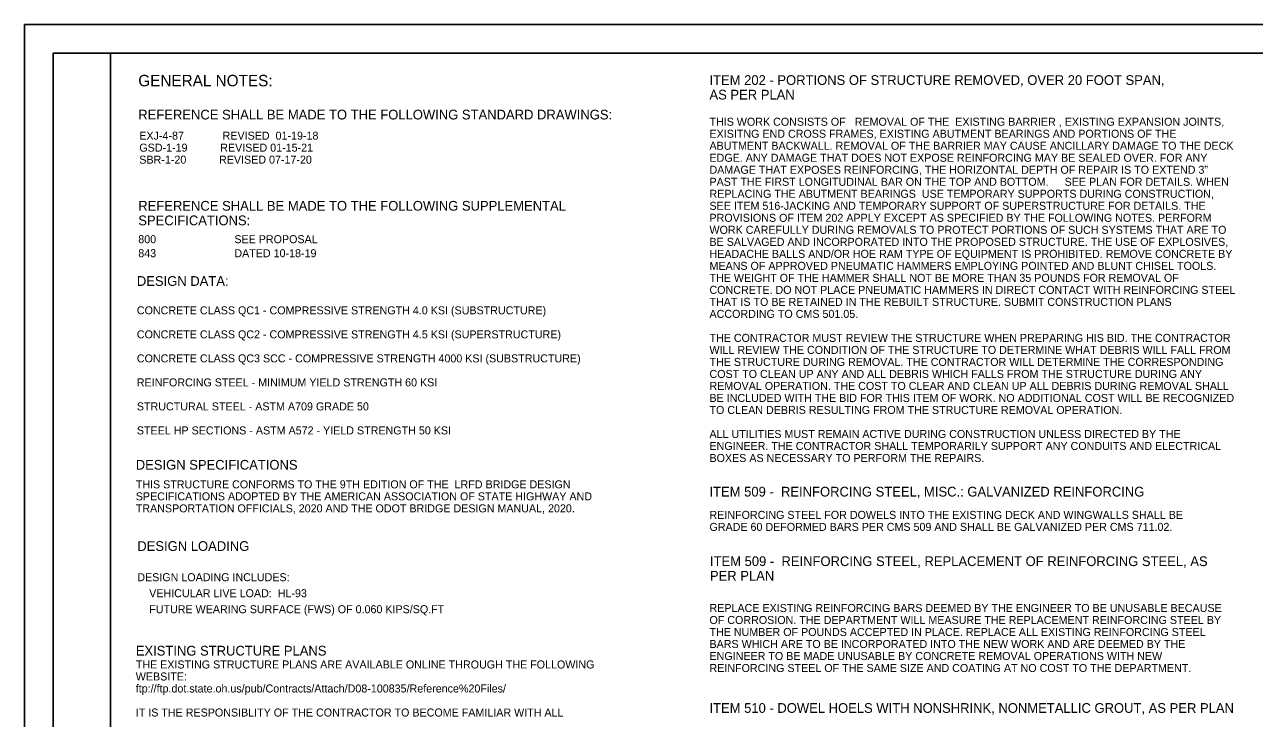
# Model space of a CAD drawing. Extents: x -17.8 to 35.4, y -13.8 to 33.2.
# Drawn here: x 0 to 21.5, y 9.87 to 22 of the extents above; entities that cross this region are included whole.
import ezdxf

# ---------------------------------------------------------------- set-up
doc = ezdxf.new("R2010")
doc.units = 0
for name, color, linetype in [('BR_P_Gen_Text', 7, 'Continuous'), ('SH_Border', 7, 'Continuous'), ('SH_Cut_Line', 7, 'Continuous'), ('SH_Text', 7, 'Continuous')]:
    doc.layers.add(name, color=color, linetype=linetype)

msp = doc.modelspace()

# ---------------------------------------------------------------- linework, layer by layer
at = {"layer": 'SH_Border'}
for points in [[(0.5, 21.5), (1.5, 21.5), (1.5, 0.5), (0.5, 0.5)], [(1.5, 21.5), (33.5, 21.5), (33.5, 0.5), (1.5, 0.5)]]:
    msp.add_lwpolyline(points, close=True, dxfattribs=at)
at = {"layer": 'SH_Cut_Line'}
msp.add_lwpolyline([(0, 0), (34, 0), (34, 22), (0, 22)], close=True, dxfattribs=at)

# ---------------------------------------------------------------- texts
at = {"layer": 'BR_P_Gen_Text'}
for s, height, p in [('GENERAL NOTES:', 0.2, (1.988, 20.921)), ('ITEM 202 - PORTIONS OF STRUCTURE REMOVED, OVER 20 FOOT SPAN, ', 0.17, (11.976, 20.945)), ('AS PER PLAN', 0.17, (11.976, 20.69)), ('REFERENCE SHALL BE MADE TO THE FOLLOWING STANDARD DRAWINGS:', 0.17, (1.988, 20.341)), ('THIS WORK CONSISTS OF ', 0.14, (11.976, 20.231)), ('REMOVAL OF THE  EXISTING BARRIER , EXISTING EXPANSION JOINTS, ', 0.14, (14.516, 20.231)), ('EXISITNG END CROSS FRAMES, EXISTING ABUTMENT BEARINGS AND PORTIONS OF THE ', 0.14, (11.976, 20.021)), ('ABUTMENT BACKWALL. REMOVAL OF THE BARRIER MAY CAUSE ANCILLARY DAMAGE TO THE DECK ', 0.14, (11.976, 19.811)), ('EDGE. ANY DAMAGE THAT DOES NOT EXPOSE REINFORCING MAY BE SEALED OVER. FOR ANY ', 0.14, (11.976, 19.601)), ('DAMAGE THAT EXPOSES REINFORCING, THE HORIZONTAL DEPTH OF REPAIR IS TO EXTEND 3” ', 0.14, (11.976, 19.391)), ('PAST THE FIRST LONGITUDINAL BAR ON THE TOP AND BOTTOM. ', 0.14, (11.976, 19.181)), ('SEE PLAN FOR DETAILS. WHEN ', 0.14, (18.186, 19.181)), ('REPLACING THE ABUTMENT BEARINGS  USE TEMPORARY SUPPORTS DURING CONSTRUCTION, ', 0.14, (11.976, 18.971)), ('REFERENCE SHALL BE MADE TO THE FOLLOWING SUPPLEMENTAL ', 0.17, (1.988, 18.746)), ('SEE ITEM 516-JACKING AND TEMPORARY SUPPORT OF SUPERSTRUCTURE FOR DETAILS. THE ', 0.14, (11.976, 18.761)), ('SPECIFICATIONS:', 0.17, (1.988, 18.491)), ('PROVISIONS OF ITEM 202 APPLY EXCEPT AS SPECIFIED BY THE FOLLOWING NOTES. PERFORM ', 0.14, (11.976, 18.551)), ('800', 0.14, (1.988, 18.177)), ('SEE PROPOSAL', 0.14, (3.668, 18.177)), ('WORK CAREFULLY DURING REMOVALS TO PROTECT PORTIONS OF SUCH SYSTEMS THAT ARE TO ', 0.14, (11.976, 18.341)), ('843', 0.14, (1.988, 17.932)), ('DATED 10-18-19', 0.14, (3.668, 17.932)), ('BE SALVAGED AND INCORPORATED INTO THE PROPOSED STRUCTURE. THE USE OF EXPLOSIVES, ', 0.14, (11.976, 18.131)), ('HEADACHE BALLS AND/OR HOE RAM TYPE OF EQUIPMENT IS PROHIBITED. REMOVE CONCRETE BY ', 0.14, (11.976, 17.921)), ('MEANS OF APPROVED PNEUMATIC HAMMERS EMPLOYING POINTED AND BLUNT CHISEL TOOLS. ', 0.14, (11.976, 17.711)), ('THE WEIGHT OF THE HAMMER SHALL NOT BE MORE THAN 35 POUNDS FOR REMOVAL OF ', 0.14, (11.976, 17.501)), ('DESIGN DATA:', 0.17, (1.963, 17.431)), ('CONCRETE. DO NOT PLACE PNEUMATIC HAMMERS IN DIRECT CONTACT WITH REINFORCING STEEL ', 0.14, (11.976, 17.291)), ('THAT IS TO BE RETAINED IN THE REBUILT STRUCTURE. SUBMIT CONSTRUCTION PLANS ', 0.14, (11.976, 17.081)), ('CONCRETE CLASS QC1 - COMPRESSIVE STRENGTH 4.0 KSI (SUBSTRUCTURE)', 0.14, (1.963, 16.933)), ('ACCORDING TO CMS 501.05.', 0.14, (11.976, 16.871)), ('CONCRETE CLASS QC2 - COMPRESSIVE STRENGTH 4.5 KSI (SUPERSTRUCTURE)', 0.14, (1.963, 16.513)), ('THE CONTRACTOR MUST REVIEW THE STRUCTURE WHEN PREPARING HIS BID. THE CONTRACTOR ', 0.14, (11.976, 16.451)), ('WILL REVIEW THE CONDITION OF THE STRUCTURE TO DETERMINE WHAT DEBRIS WILL FALL FROM ', 0.14, (11.976, 16.241)), ('CONCRETE CLASS QC3 SCC - COMPRESSIVE STRENGTH 4000 KSI (SUBSTRUCTURE)', 0.14, (1.963, 16.093)), ('THE STRUCTURE DURING REMOVAL. THE CONTRACTOR WILL DETERMINE THE CORRESPONDING ', 0.14, (11.976, 16.031)), ('COST TO CLEAN UP ANY AND ALL DEBRIS WHICH FALLS FROM THE STRUCTURE DURING ANY ', 0.14, (11.976, 15.821)), ('REINFORCING STEEL - MINIMUM YIELD STRENGTH 60 KSI', 0.14, (1.963, 15.673)), ('REMOVAL OPERATION. THE COST TO CLEAR AND CLEAN UP ALL DEBRIS DURING REMOVAL SHALL ', 0.14, (11.976, 15.611)), ('BE INCLUDED WITH THE BID FOR THIS ITEM OF WORK. NO ADDITIONAL COST WILL BE RECOGNIZED ', 0.14, (11.976, 15.401)), ('STRUCTURAL STEEL - ASTM A709 GRADE 50', 0.14, (1.963, 15.253)), ('TO CLEAN DEBRIS RESULTING FROM THE STRUCTURE REMOVAL OPERATION.', 0.14, (11.976, 15.191)), ('STEEL HP SECTIONS - ASTM A572 - YIELD STRENGTH 50 KSI', 0.14, (1.963, 14.833)), ('ALL UTILITIES MUST REMAIN ACTIVE DURING CONSTRUCTION UNLESS DIRECTED BY THE ', 0.14, (11.976, 14.771)), ('ENGINEER. THE CONTRACTOR SHALL TEMPORARILY SUPPORT ANY CONDUITS AND ELECTRICAL ', 0.14, (11.976, 14.561)), ('BOXES AS NECESSARY TO PERFORM THE REPAIRS.', 0.14, (11.976, 14.351)), ('DESIGN SPECIFICATIONS', 0.17, (1.944, 14.217)), ('ITEM 509 -  REINFORCING STEEL, MISC.: GALVANIZED REINFORCING', 0.17, (11.976, 13.747)), ('REINFORCING STEEL FOR DOWELS INTO THE EXISTING DECK AND WINGWALLS SHALL BE ', 0.14, (11.976, 13.356)), ('GRADE 60 DEFORMED BARS PER CMS 509 AND SHALL BE GALVANIZED PER CMS 711.02.', 0.14, (11.976, 13.146)), ('ITEM 509 -  REINFORCING STEEL, REPLACEMENT OF REINFORCING STEEL, AS ', 0.17, (11.984, 12.531)), ('PER PLAN', 0.17, (11.984, 12.276)), ('REPLACE EXISTING REINFORCING BARS DEEMED BY THE ENGINEER TO BE UNUSABLE BECAUSE ', 0.14, (11.976, 11.728)), ('OF CORROSION. THE DEPARTMENT WILL MEASURE THE REPLACEMENT REINFORCING STEEL BY ', 0.14, (11.976, 11.518)), ('THE NUMBER OF POUNDS ACCEPTED IN PLACE. REPLACE ALL EXISTING REINFORCING STEEL ', 0.14, (11.976, 11.308)), ('BARS WHICH ARE TO BE INCORPORATED INTO THE NEW WORK AND ARE DEEMED BY THE ', 0.14, (11.976, 11.098)), ('EXISTING STRUCTURE PLANS', 0.17, (1.944, 10.966)), ('ENGINEER TO BE MADE UNUSABLE BY CONCRETE REMOVAL OPERATIONS WITH NEW ', 0.14, (11.976, 10.888)), ('THE EXISTING STRUCTURE PLANS ARE AVAILABLE ONLINE THROUGH THE FOLLOWING ', 0.14, (1.944, 10.74)), ('REINFORCING STEEL OF THE SAME SIZE AND COATING AT NO COST TO THE DEPARTMENT. ', 0.14, (11.976, 10.678)), ('WEBSITE:', 0.14, (1.944, 10.53)), ('ftp://ftp.dot.state.oh.us/pub/Contracts/Attach/D08-100835/Reference%20Files/', 0.14, (1.944, 10.32)), ('ITEM 510 - DOWEL HOELS WITH NONSHRINK, NONMETALLIC GROUT, AS PER PLAN', 0.17, (11.976, 9.964)), ('IT IS THE RESPONSIBLITY OF THE CONTRACTOR TO BECOME FAMILIAR WITH ALL ', 0.14, (1.944, 9.9))]:
    msp.add_text(s, height=height, rotation=0, dxfattribs=at).set_placement(p)
for s, p in [('EXJ-4-87             REVISED  01-19-18', (2.006, 19.988)), ('GSD-1-19           REVISED 01-15-21', (2.006, 19.778)), ('SBR-1-20           REVISED 07-17-20', (2.006, 19.568)), ('THIS STRUCTURE CONFORMS TO THE 9TH EDITION OF THE  LRFD BRIDGE DESIGN ', (1.944, 13.89)), ('SPECIFICATIONS ADOPTED BY THE AMERICAN ASSOCIATION OF STATE HIGHWAY AND ', (1.944, 13.68)), ('TRANSPORTATION OFFICIALS, 2020 AND THE ODOT BRIDGE DESIGN MANUAL, 2020.', (1.944, 13.47))]:
    msp.add_text(s, height=0.14, dxfattribs=at).set_placement(p)
at = {"layer": 'SH_Text'}
for s, height, p in [('DESIGN LOADING', 0.17, (1.971, 12.796)), ('DESIGN LOADING INCLUDES:', 0.14, (1.971, 12.266)), ('    VEHICULAR LIVE LOAD:  HL-93', 0.14, (1.971, 11.986)), ('    FUTURE WEARING SURFACE (FWS) OF 0.060 KIPS/SQ.FT', 0.14, (1.971, 11.706))]:
    msp.add_text(s, height=height, dxfattribs=at).set_placement(p)

doc.saveas('drawing.dxf')
